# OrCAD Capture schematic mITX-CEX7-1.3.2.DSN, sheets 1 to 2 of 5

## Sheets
1 CEX7-Interface: size D; title: COM express type 7 interface; rev: 1.3
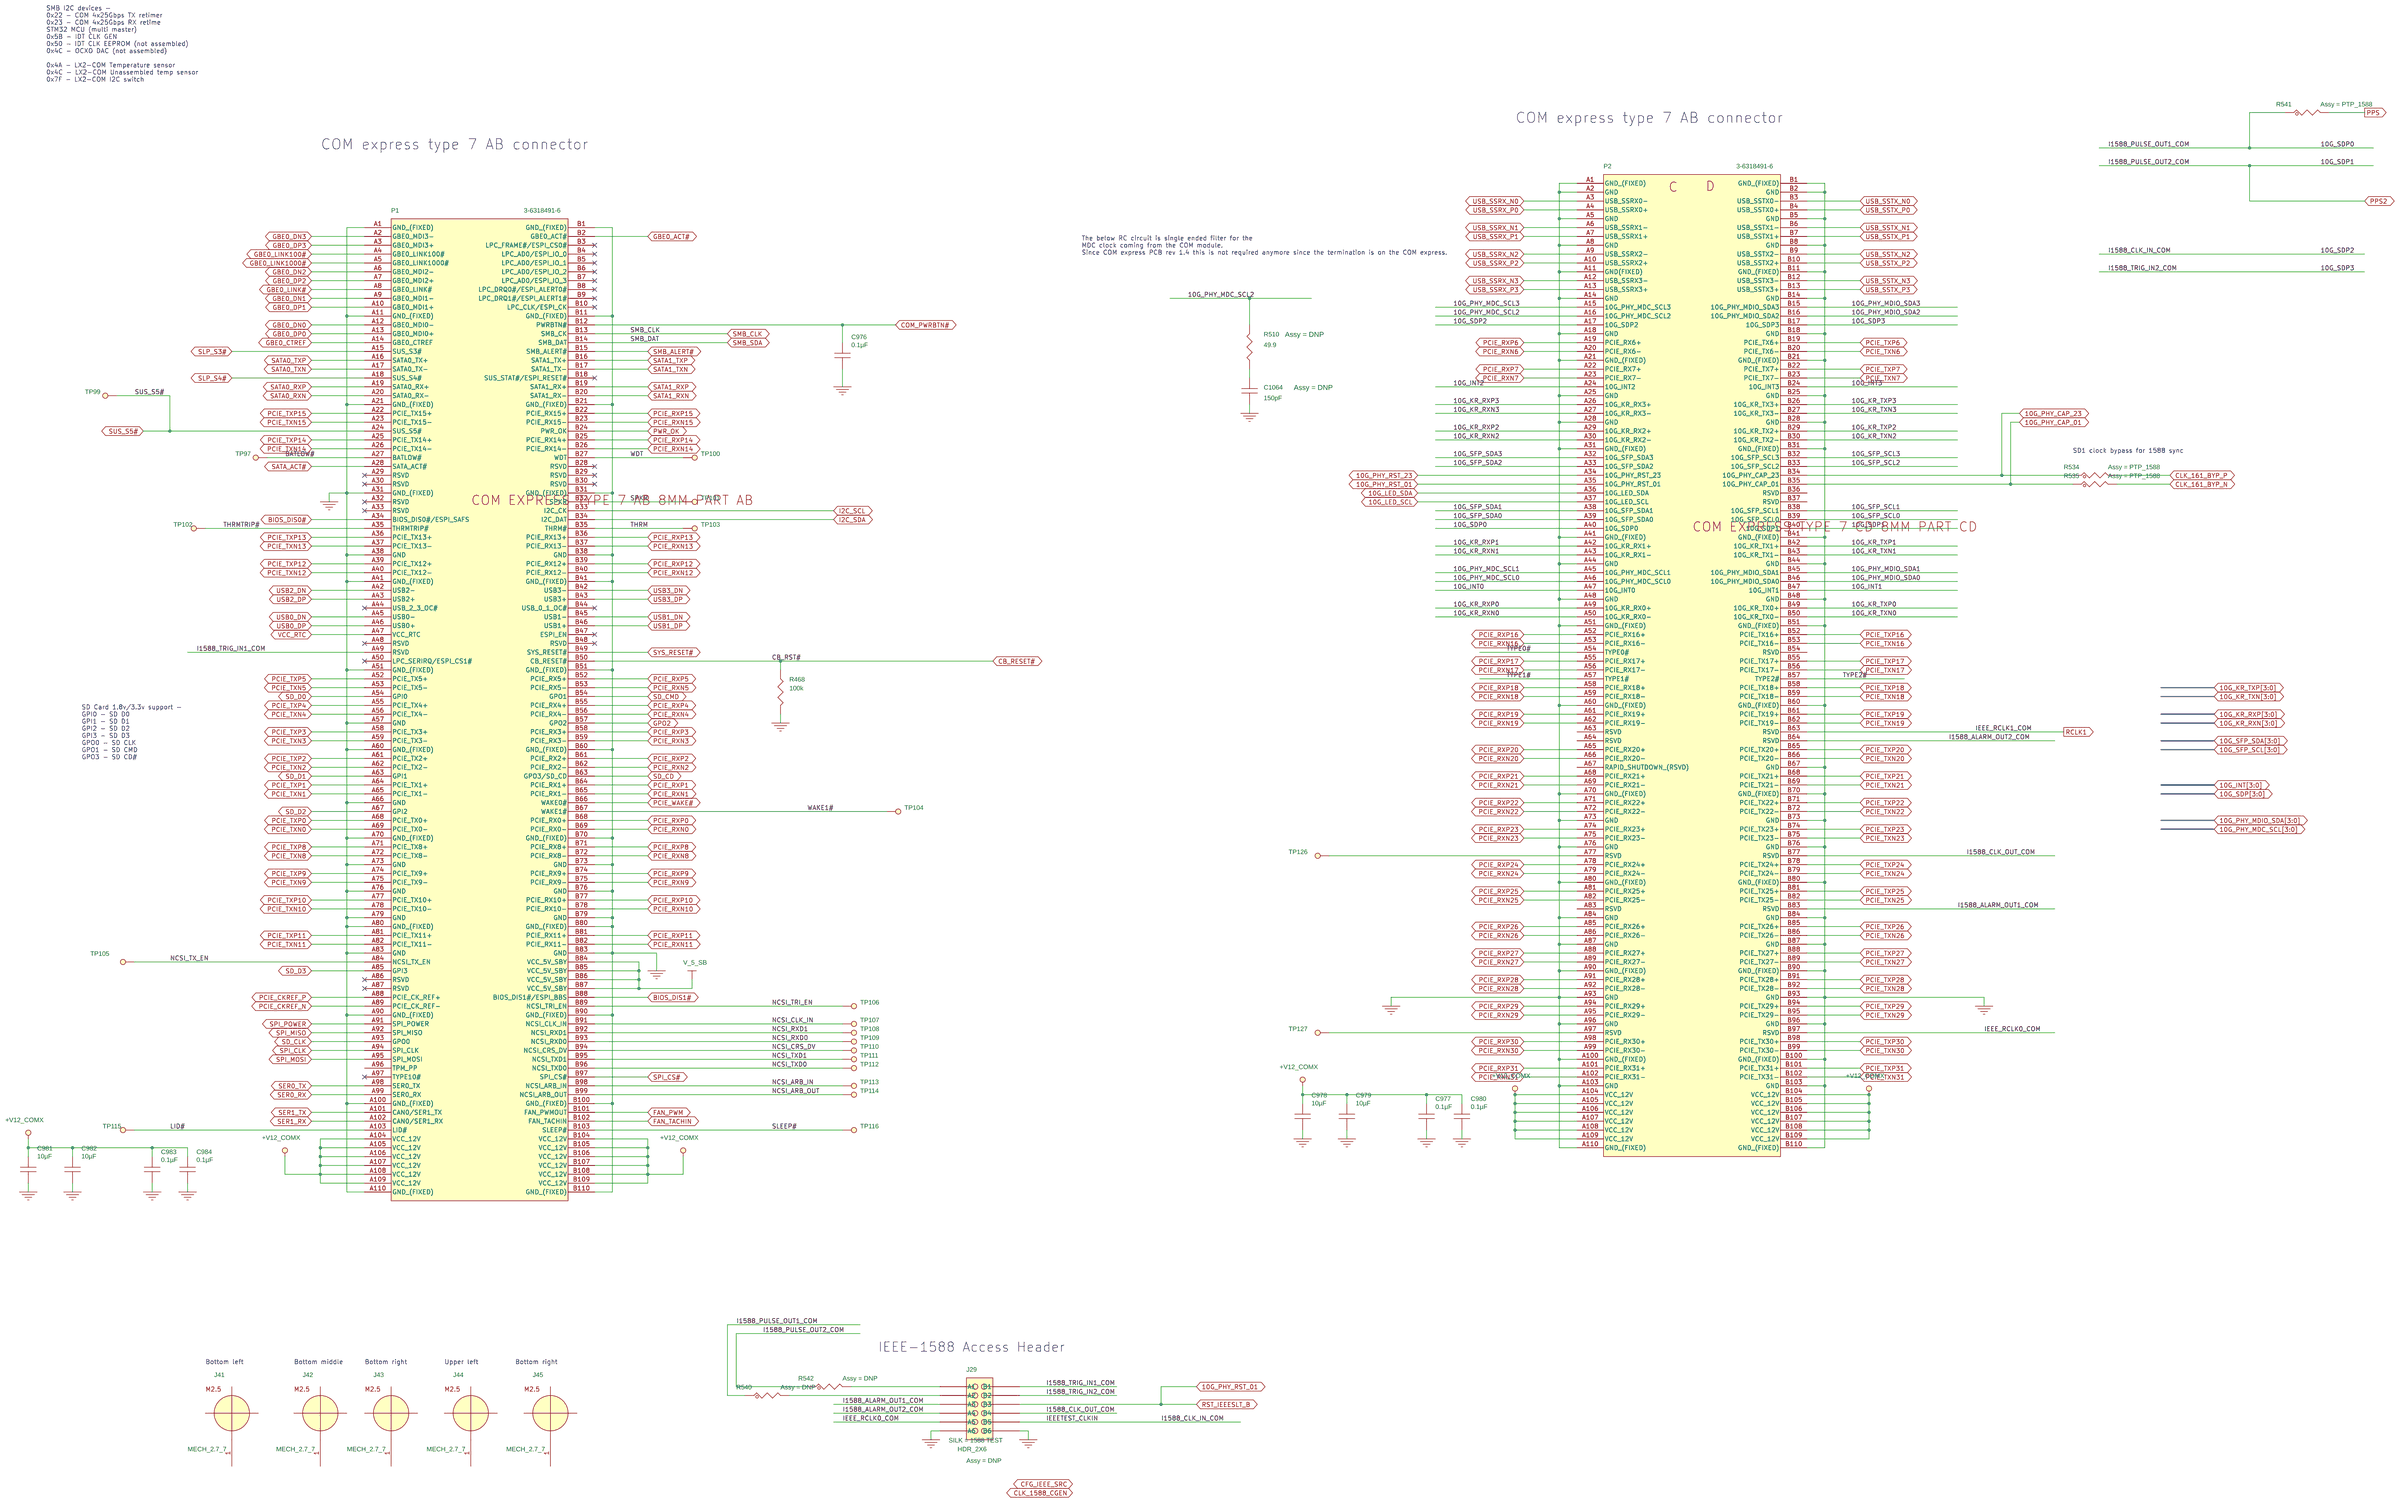
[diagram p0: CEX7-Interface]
2 Connectors: size D; title: PCIe, SATA, NVME, FANs, micro SD, RJ45 and QSFP28 connectors
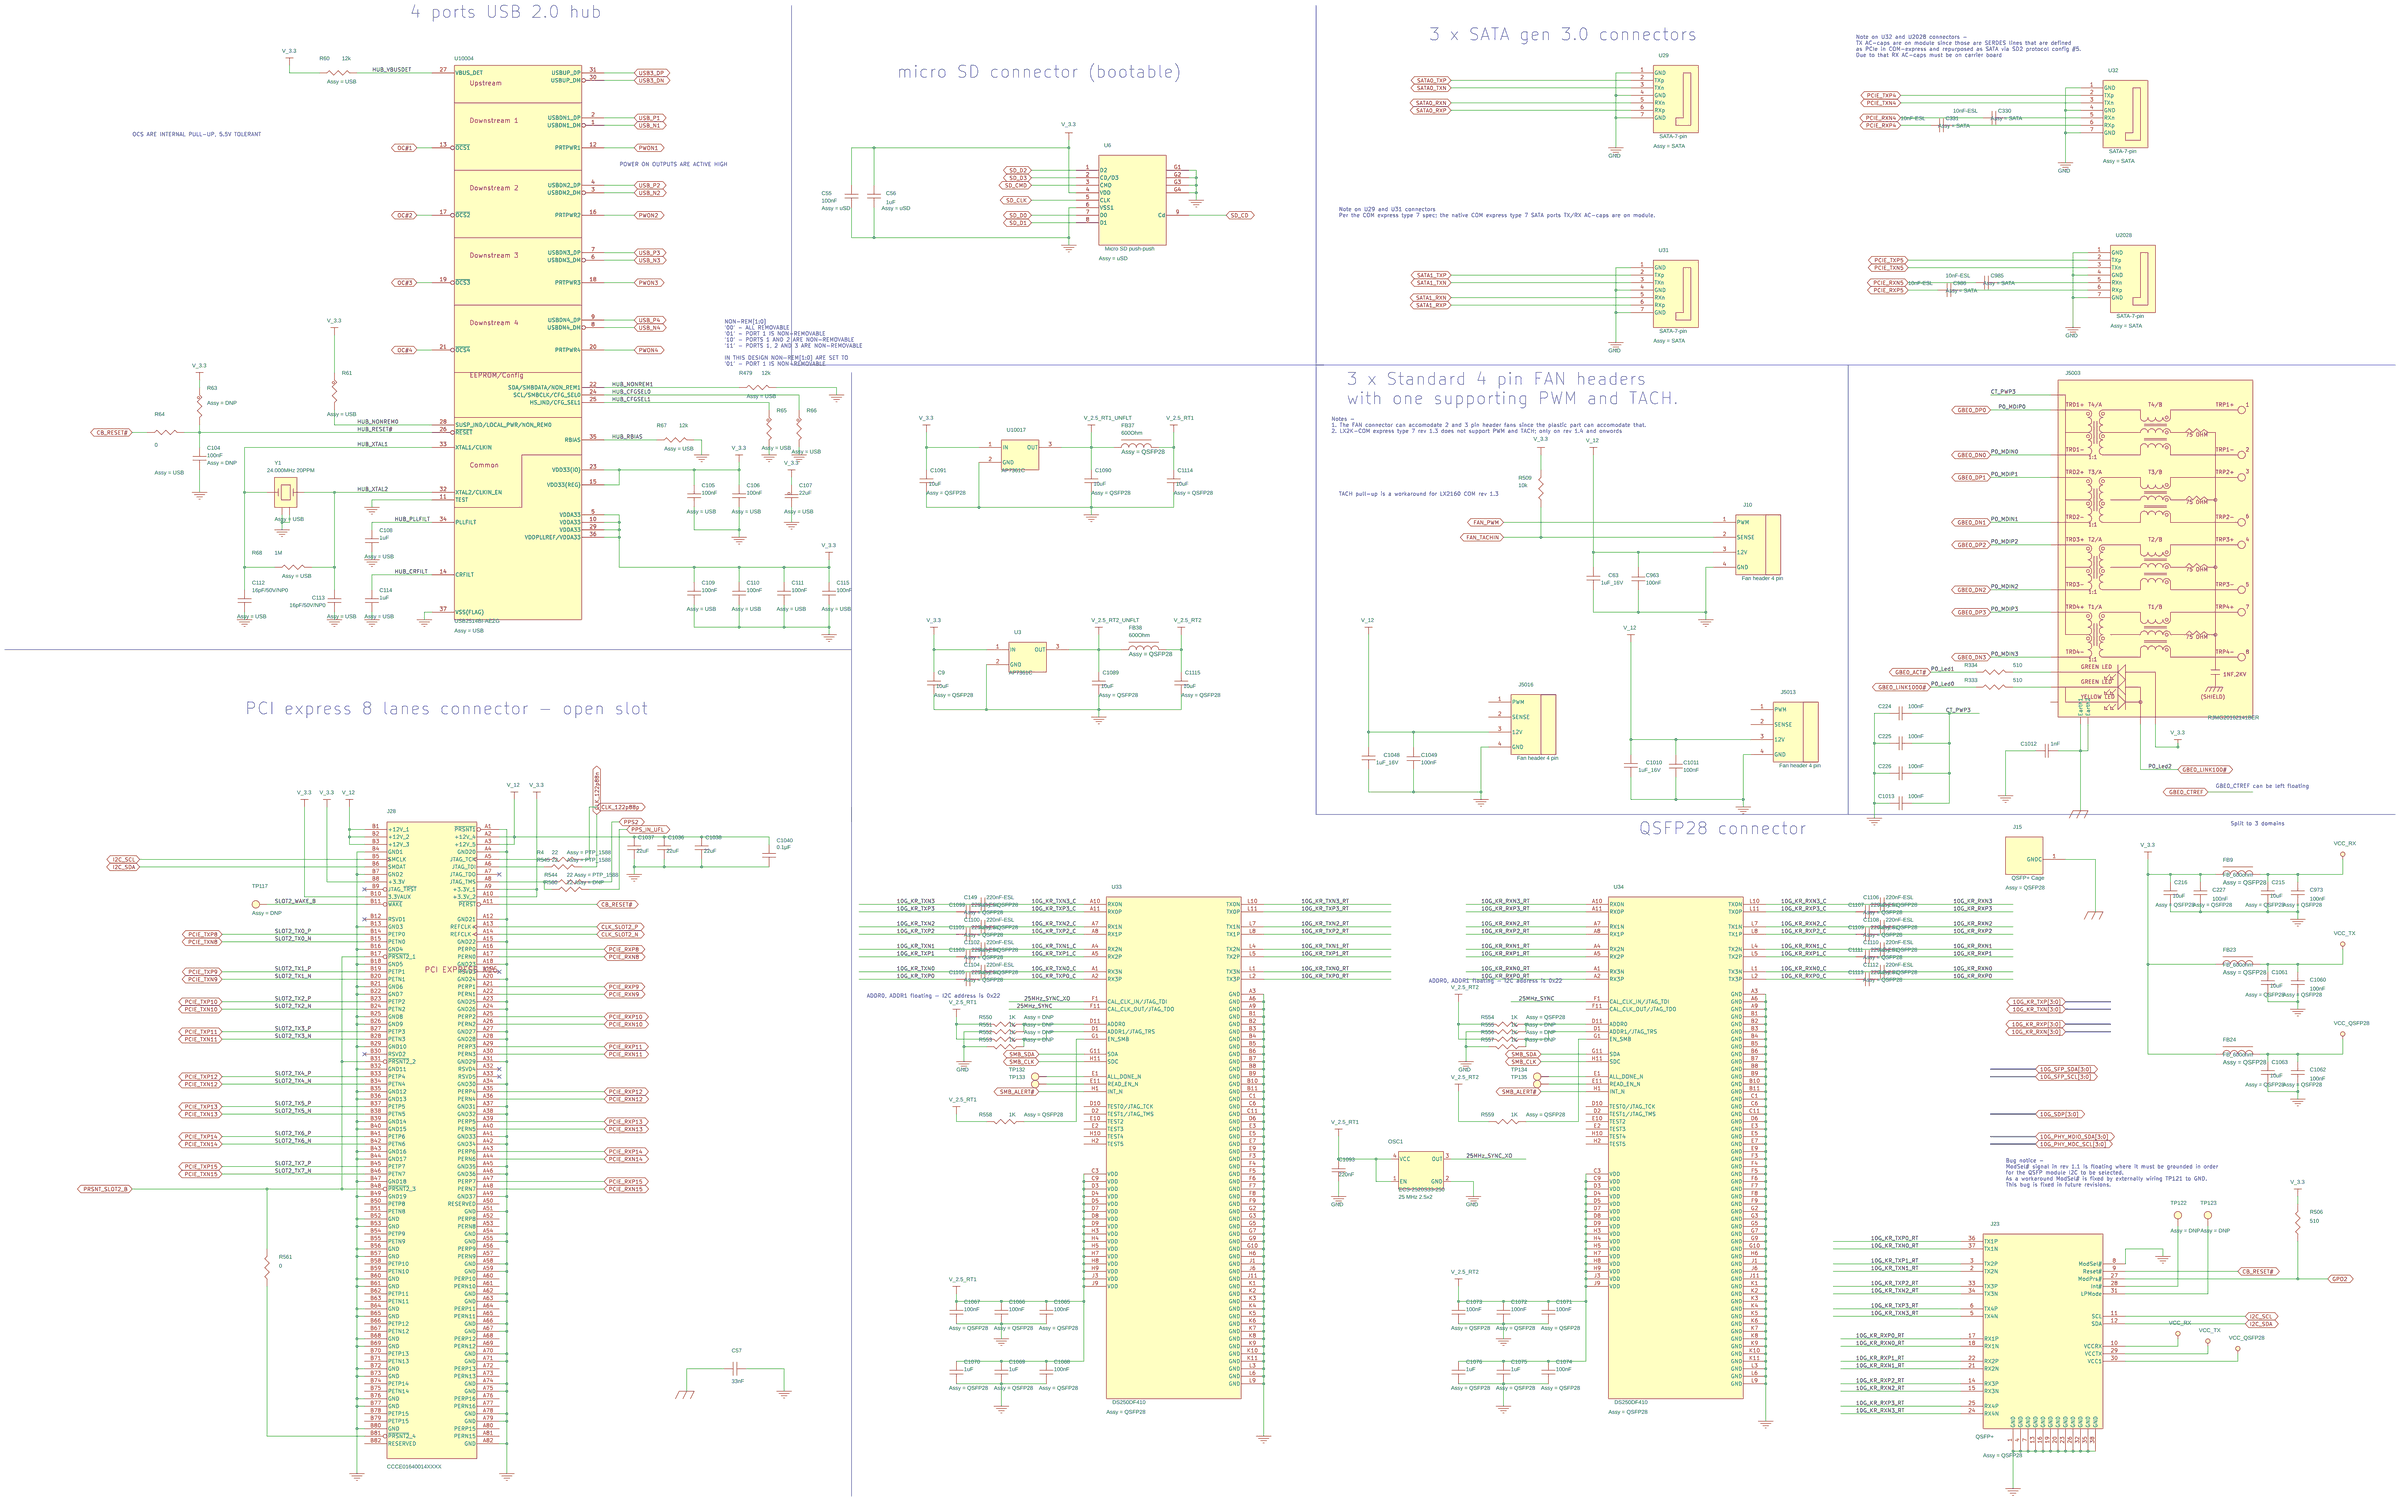
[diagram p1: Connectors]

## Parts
sheet CEX7-Interface
C976  0.1µF  [RC0402]
C977  0.1µF  [RC0402]
C978  10µF  [RC0805]
C979  10µF  [RC0805]
C980  0.1µF  [RC0402]
C981  10µF  [RC0805]
C982  10µF  [RC0805]
C983  0.1µF  [RC0402]
C984  0.1µF  [RC0402]
C1064  150pF
J29  HDR_2X6  [tsm2x6_smd]
J41  MECH_2.7_7  [MECH_2.5_4]
J42  MECH_2.7_7  [MECH_2.5_4]
J43  MECH_2.7_7  [MECH_2.5_4]
J44  MECH_2.7_7  [MECH_2.5_4]
J45  MECH_2.7_7  [MECH_2.5_4]
P1  3-6318491-6  [A107335-ND-AB]
P2  3-6318491-6  [A107335-ND-CD]
R468  100k  [RC0402]
R510  49.9
R534  0  [0402]
R535  0  [0402]
R540  0  [0402]
R541  0  [0402]
R542  0  [0402]
TP97  TESTPOINT  [TESTPOINT]
TP99  TESTPOINT  [TESTPOINT]
TP100  TESTPOINT  [TESTPOINT]
TP101  TESTPOINT  [TESTPOINT]
TP102  TESTPOINT  [TESTPOINT]
TP103  TESTPOINT  [TESTPOINT]
TP104  TESTPOINT  [TESTPOINT]
TP105  TESTPOINT  [TESTPOINT]
TP106  TESTPOINT  [TESTPOINT]
TP107  TESTPOINT  [TESTPOINT]
TP108  TESTPOINT  [TESTPOINT]
TP109  TESTPOINT  [TESTPOINT]
TP110  TESTPOINT  [TESTPOINT]
TP111  TESTPOINT  [TESTPOINT]
TP112  TESTPOINT  [TESTPOINT]
TP113  TESTPOINT  [TESTPOINT]
TP114  TESTPOINT  [TESTPOINT]
TP115  TESTPOINT  [TESTPOINT]
TP116  TESTPOINT  [TESTPOINT]
TP126  TESTPOINT  [TESTPOINT]
TP127  TESTPOINT  [TESTPOINT]
sheet Connectors
C9  10uF  [C0603]
C55  100nF
C56  1uF
C57  33nF
C63  1uF_16V
C104  100nF
C105  100nF
C106  100nF
C107  22uF
C108  1uF
C109  100nF
C110  100nF
C111  100nF
C112  16pF/50V/NP0  [1276-1646-1-ND]
C113  16pF/50V/NP0  [1276-1646-1-ND]
C114  1uF
C115  100nF
C149  220nF-ESL  [C0402]
C215  10uF
C216  10uF
C224  100nF
C225  100nF
C226  100nF
C227  100nF
C330  10nF-ESL
C331  10nF-ESL
C963  100nF
C973  100nF
C985  10nF-ESL
C986  10nF-ESL
C1010  1uF_16V
C1011  100nF
C1012  1nF
C1013  100nF
C1036  22uF
C1037  22uF
C1038  22uF
C1040  0.1µF  [RC0402]
C1048  1uF_16V
C1049  100nF
C1060  100nF
C1061  10uF
C1062  100nF
C1063  10uF
C1065  100nF
C1066  100nF
C1067  100nF
C1068  100nF
C1069  1uF
C1070  1uF
C1071  100nF
C1072  100nF
C1073  100nF
C1074  100nF
C1075  1uF
C1076  1uF
C1089  10uF  [C0603]
C1090  10uF  [C0603]
C1091  10uF  [C0603]
C1093  220nF  [C0402]
C1099  220nF-ESL  [C0402]
C1100  220nF-ESL  [C0402]
C1101  220nF-ESL  [C0402]
C1102  220nF-ESL  [C0402]
C1103  220nF-ESL  [C0402]
C1104  220nF-ESL  [C0402]
C1105  220nF-ESL  [C0402]
C1106  220nF-ESL  [C0402]
C1107  220nF-ESL  [C0402]
C1108  220nF-ESL  [C0402]
C1109  220nF-ESL  [C0402]
C1110  220nF-ESL  [C0402]
C1111  220nF-ESL  [C0402]
C1112  220nF-ESL  [C0402]
C1113  220nF-ESL  [C0402]
C1114  10uF  [C0603]
C1115  10uF  [C0603]
FB9  FB_600ohm
FB23  FB_600ohm
FB24  FB_600ohm
FB37  600Ohm  [L0603]
FB38  600Ohm  [L0603]
J10  Fan header 4 pin  [22-23-2041]
J15  QSFP+ Cage
J23  QSFP+
J28  CCCE01640014XXXX
J5003  RJMG20162141BER
J5013  Fan header 4 pin  [22-23-2041]
J5016  Fan header 4 pin  [22-23-2041]
OSC1  ECS-2520S33-250  [ECS-2520S33-250-FN-TR]
R4  22  [R0402]
R60  12k  [RC0402]
R61  100K
R63  100K
R64  0  [RC0402]
R65  100K
R66  100K
R67  12k  [RC0402]
R68  1M  [RC0402]
R333  510
R334  510
R479  12k  [RC0402]
R506  510
R509  10k
R544  22  [R0402]
R545  22  [R0402]
R550  1K
R551  1K
R552  1K
R553  1K
R554  1K
R555  1K
R556  1K
R557  1K
R558  1K
R559  1K
R560  22  [R0402]
R561  0  [RC0402]
TP117  TP
TP122  TP
TP123  TP
TP132  TP
TP133  TP
TP134  TP
TP135  TP
U3  AP7361C  [SOT223]
U6  Micro SD push-push  [CJ-WK21923-R6SS6]
U29  SATA-7-pin  [SATA-7-PIN]
U31  SATA-7-pin  [SATA-7-PIN]
U32  SATA-7-pin  [SATA-7-PIN]
U33  DS250DF410
U34  DS250DF410
U2028  SATA-7-pin  [SATA-7-PIN]
U10004  USB2514BI-AEZG  [USB2514BI-AEZG-ND]
U10017  AP7361C  [SOT223]
Y1  24.000MHz 20PPM  [SER3634CT-ND]

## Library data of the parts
C976 C977 C980 C983 C984 C1040 = CAP_CER_0.1UF_16V_10%_X7R_0402: SolidRun P/N: CA20013
C978 C979 C981 C982 = CAP_CER_10UF_25V_10%_X5R_0805: SolidRun P/N: CA40005
C1064 = Cap: CAP CER 0402 150pF 50V 5% COG; Assy: DNP; SolidRun P/N: CA20827
J29 = CONN_HDR_6X2: HDR 2X6 SMT 100MIL SP 380H AU; AGILE_PN: 211-75508; Assy: DNP; CAD_APPROVED: Yes; HEIGHT: 9.65mm; MFG_NAME01: SAMTEC; MFG_PN01: TSM-106-01-S-DV-A-P; ROHS: Yes; SILK: 1588 TEST; SolidRun P/N: CO00807
J41-J45 = MECH_0.5_4: SolidRun P/N: MCH00072
P1 = COM-EXPRESS_BASE_TYP_7_CONN_AB: SolidRun P/N: CO00676
P2 = COM-EXPRESS_BASE_TYP_7_CONN_CD: SolidRun P/N: CO00676
R468 = RES_100K_OHM_1_16W_1%_0402_SMD: SolidRun P/N: RE20482
R510 = Resistor: RES 0402 1/16W 49.9 1%; Assy: DNP; SolidRun P/N: RE20011
R534 R535 R541 = RES: RES MF ZERO OHM 1/10W -- 0402; AGILE_PN: 470-79965; Assy: PTP_1588; CAD_APPROVED: Yes; FPLIST: RC0402_25,RC0402_HD,RC0402_X2,0402_CC; PRIORITY_PN: RE20009; ROHS: Yes; SIGNAL_MODEL: DEFAULT_RESISTOR_0.001OHM_2_1; SolidRun P/N: RE20009
R540 R542 = RES: RES MF ZERO OHM 1/10W -- 0402; AGILE_PN: 470-79965; Assy: DNP; CAD_APPROVED: Yes; FPLIST: RC0402_25,RC0402_HD,RC0402_X2,0402_CC; PRIORITY_PN: RE20009; ROHS: Yes; SIGNAL_MODEL: DEFAULT_RESISTOR_0.001OHM_2_1; SolidRun P/N: RE20009
TP97 TP99-TP116 TP126 TP127 = TESTPOINT: Assy: DNP; SolidRun P/N: TP00001
C9 C1089-C1091 C1114 C1115 = Cap: CAP CER 0603 10UF 6.3V 10% X5R; Assy: QSFP28; Manufacturer: Samsung; Manufacturer Name: Samsung; Manufacturer P/N: CL10A106KQ8NNNC; Part Number: C1060805-X5R-16V; SolidRun P/N: CA30001; Updated: 2016-02-10 17:13:33; Datasheet: <null>
C55 = Cap: Assy: uSD; SolidRun P/N: CA20001
C56 = Cap: Assy: uSD; SolidRun P/N: CA20005
C57 = Cap: SolidRun P/N: CA20011
C63 C1010 C1048 = Cap: SolidRun P/N: CA30013
C104 = Cap: CAP CER 0402 100nF 10V 10% X7R; Assy: DNP; SolidRun P/N: CA20001
C105 C106 C109-C111 C115 = Cap: CAP CER 0402 100nF 10V 10% X7R; Assy: USB; SolidRun P/N: CA20001
C107 = CAP_NP: CAP CER 22UF 6.3V 20% X5R 0603; Assy: USB; SolidRun P/N: CA30002
C108 C114 = Cap: CAP CER 1uF 10V 10% X5R 0402; Assy: USB; SolidRun P/N: CA20005
C112 C113 = CAP_CER_16PF_50V_5%_NP0_0402: Assy: USB; SolidRun P/N: CA20134
C149 C1099-C1113 = Cap: CAP CER 220nF 16V 10% X7R 0402; Assy: QSFP28; FPLIST: 0402_SQR21,0402_RND,0402; Manufacturer: CAPAX; Manufacturer P/N: 0402X224K250SNT; Part Number: 0402X224K250SNT; SolidRun P/N: CA20826; Updated: 2015-02-17 20:35:06; Datasheet: <null>
C215 C216 C1061 C1063 = Cap: CAP CER 10UF 6.3V 10% X5R 0603; Assy: QSFP28; SolidRun P/N: CA30001
C224-C226 C1013 = CAP_NP1: CAP CER 0.1uF ±10% 50V X7R 0402; SolidRun P/N: CA20147
C227 C973 C1060 C1062 = Cap: CHIP CAP 0.1uF 6.3V 0402 X5R; Assy: QSFP28; SolidRun P/N: CA20001
C330 C331 C985 C986 = Cap: Assy: SATA; SolidRun P/N: CA20002
C963 C1011 C1049 = Cap: SolidRun P/N: CA20001
C1012 = CAP_NP1: CAP CER 1nF ±10% 1KV X7R 1206; SolidRun P/N: CA50002
C1036-C1038 = Cap: SolidRun P/N: CA60006
C1065-C1068 C1071-C1074 = Cap: CAP CER 0402 100nF 10V 10% X7R; Assy: QSFP28; SolidRun P/N: CA20001
C1069 C1070 C1075 C1076 = Cap: CAP CER 1uF 10V 10% X5R 0402; Assy: QSFP28; SolidRun P/N: CA20005
C1093 = CAP_NP1: CAP CER 0.22UF 16V X7R 0402; Assy: QSFP28; Digikey P/N: 490-5418-2-ND; Manufacturer: Murata Electronics North America; Part Num#: GRM155R71C224KA12D; Rating: 16V; SolidRun P/N: CA20820; Vol: 10%
FB9 FB23 FB24 = Ferrite_Bead_v3: Multilayer Ferrite Chip Beads 0603 600ohm 1.3A +/-25%; Assy: QSFP28; SolidRun P/N: IN00068
FB37 FB38 = Ferrite_Bead_v3: Multilayer Ferrite Chip Beads 600 OHM; Assy: QSFP28; Manufacturer: chilisin; Manufacturer P/N: PBY160808T-601Y-N; Part Number: PBY160808T-601Y-N; SolidRun P/N: IN00012; Updated: 2015-02-17 20:35:06; Datasheet: http://www.chilisin.com.tw/proimages/product_line_up_pdf/Chip%20Beads%20PB%20Series.pdf
J10 J5013 J5016 = Fan_header_4_pin: SolidRun P/N: CO00640
J15 = QSFP+_Cage: Assy: QSFP28; SolidRun P/N: CO00707
J23 = QSFP+: Assy: QSFP28; SolidRun P/N: CO00706
J28 = CONN_PCI_EXPRESS_X8_0: CON 2X62 PCI EXPRESS SMT 1MM SP 320H AU; SolidRun P/N: CO00808
J5003 = J-RJMG20162141BER-FCI: CONN MAGJACK 1PORT 1000 BASE-T; SolidRun P/N: CO00673
OSC1 = OSC_ECS-2520S: 25MHz XO (Standard) HCMOS Oscillator 3.3V Enable/Disable 4-SMD, No Lead; Assy: QSFP28; Digikey P/N: ECS Inc.; Manufacturer: ECS Inc.; Rating: 25 MHz 2.5x2; SolidRun P/N: OC00039; Datasheet: https://www.ecsxtal.com/store/pdf/ECS-2520S.pdf
R4 R544 R545 = Resistor: RES 0402 1/16W 22? 5%; Assy: PTP_1588; Manufacturer: Yageo; Manufacturer P/N: RC0402JR-0722RL; Part Number: R2200402-1%; Power: <null>; SolidRun P/N: RE20021; Tolerance: 5%; Datasheet: <null>
R60 R67 R479 = RES_12.0K_OHM_1_16W_1%_0402_SMD: Assy: USB; SolidRun P/N: RE20462
R61 R65 R66 = RES: RES MF 100K 1/16W 0402; Assy: USB; SolidRun P/N: RE20015
R63 = RES: RES MF 100K 1/16W 0402; Assy: DNP; SolidRun P/N: RE20015
R64 = RES_0.0_OHM_1_16W_0402_SMD: Assy: USB; SolidRun P/N: RE20009
R68 = RES_1.00M_OHM_1_16W_1%_0402_SMD: Assy: USB; SolidRun P/N: RE20416
R333 R334 R506 = RES1: RES SMD 510 OHM 5% 1/16W 0402; SolidRun P/N: RE20022
R509 = Resistor: RES 0402 1/16W 10K? 1%; SolidRun P/N: RE20013
R550-R553 R555-R557 = Resistor: RES 0402 1/16W 1K 5%; Assy: DNP; SolidRun P/N: RE20010
R554 R558 R559 = Resistor: RES 0402 1/16W 1K 5%; Assy: QSFP28; SolidRun P/N: RE20010
R560 = Resistor: RES 0402 1/16W 22? 5%; Assy: DNP; Manufacturer: Yageo; Manufacturer P/N: RC0402JR-0722RL; Part Number: R2200402-1%; Power: <null>; SolidRun P/N: RE20021; Tolerance: 5%; Datasheet: <null>
R561 = RES_0.0_OHM_1_16W_0402_SMD: SolidRun P/N: RE20009
TP117 TP122 TP123 TP132-TP135 = TestPoint: Assy: DNP; SolidRun P/N: TP00001
U3 U10017 = AP7361C_0: 1A, 2.5V fixed output voltage LDO; Assy: QSFP28; Manufacturer: Diodes; Manufacturer Name: Diodes; Manufacturer P/N: AP7361C-25E-13; SolidRun P/N: IC01072; Datasheet: http://www.diodes.com/_files/datasheets/AP7361.pdf
U6 = CJ-WK21923-R6SS6_0: Assy: uSD; SolidRun P/N: CO00091
U29 U31 U32 U2028 = SATA-7-pin: Assy: SATA; SolidRun P/N: CO00581
U33 U34 = DS250DF410: Assy: QSFP28; SolidRun P/N: IC01524
U10004 = IC_USB_2.0_HUB_4P_IND_36QFNE3: Assy: USB; SolidRun P/N: IC01084
Y1 = CRYSTAL_24MHZ_9PF_40Ohm_20ppm: Assy: USB; SolidRun P/N: OC00003

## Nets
3.3V: C9.1 C55.1 C56.1 C105.1 C106.1 C107.1 C109.1 C110.1 C111.1 C115.1 C216.1 C227.1 C1091.1 FB9.1 FB23.1 FB24.1 J28.A9(+3.3V_1) J28.A10(+3.3V_2) J28.B8(+3.3V) J28.B10(3.3VAUX) J5003.13 R60.1 R61.1 R63.1 R506.2 R509.2 U3.1(IN) U6.4(VDD) U10004.5(VDDA33) U10004.10(VDDA33) U10004.15(VDD33(REG)) U10004.23(VDD33(IO)) U10004.29(VDDA33) U10004.36(VDDPLLREF/VDDA33) U10017.1(IN) ; also on sheet 3 4 5
+V12_COMX: C63.1 C963.2 C977.1 C978.1 C979.1 C980.1 C981.1 C982.1 C983.1 C984.1 C1010.1 C1011.2 C1036.1 C1037.1 C1038.1 C1040.1 C1048.1 C1049.2 J10.3(12V) J28.A2(+12V_4) J28.A3(+12V_5) J28.B1(+12V_1) J28.B2(+12V_2) J28.B3(+12V_3) J5013.3(12V) J5016.3(12V) P1.A104(VCC_12V) P1.A105(VCC_12V) P1.A106(VCC_12V) P1.A107(VCC_12V) P1.A108(VCC_12V) P1.A109(VCC_12V) P1.B104(VCC_12V) P1.B105(VCC_12V) P1.B106(VCC_12V) P1.B107(VCC_12V) P1.B108(VCC_12V) P1.B109(VCC_12V) P2.A104(VCC_12V) P2.A105(VCC_12V) P2.A106(VCC_12V) P2.A107(VCC_12V) P2.A108(VCC_12V) P2.A109(VCC_12V) P2.B104(VCC_12V) P2.B105(VCC_12V) P2.B106(VCC_12V) P2.B107(VCC_12V) P2.B108(VCC_12V) P2.B109(VCC_12V) ; also on sheet 3 4
GND: C9.2 C55.2 C56.2 C57.2 C63.2 C104.2 C105.2 C106.2 C107.2 C108.2 C109.2 C110.2 C111.2 C112.2 C113.2 C114.2 C115.2 C215.2 C216.2 C224.1 C225.1 C226.1 C227.2 C963.1 C973.2 C976.2 C977.2 C978.2 C979.2 C980.2 C981.2 C982.2 C983.2 C984.2 C1010.2 C1011.1 C1012.2 C1013.1 C1036.2 C1037.2 C1038.2 C1040.2 C1048.2 C1049.1 C1060.2 C1061.2 C1062.2 C1063.2 C1064.2 C1065.2 C1066.2 C1067.2 C1068.2 C1069.2 C1070.2 C1071.2 C1072.2 C1073.2 C1074.2 C1075.2 C1076.2 C1089.2 C1090.2 C1091.2 C1093.2 C1114.2 C1115.2 J10.4(GND) J23.1(GND) J23.4(GND) J23.7(GND) J23.8(ModSeI#) J23.13(GND) J23.16(GND) J23.19(GND) J23.20(GND) J23.23(GND) J23.26(GND) J23.32(GND) J23.35(GND) J23.38(GND) J28.A1(~{PRSNT1}) J28.A4(GND20) J28.A12(GND21) J28.A15(GND22) J28.A18(GND23) J28.A20(GND24) J28.A23(GND25) J28.A24(GND26) J28.A27(GND27) J28.A28(GND28) J28.A31(GND29) J28.A34(GND30) J28.A37(GND31) J28.A38(GND32) J28.A41(GND33) J28.A42(GND34) J28.A45(GND35) J28.A46(GND36) J28.A49(GND37) J28.A51(GND) J28.A54(GND) J28.A55(GND) J28.A58(GND) J28.A59(GND) J28.A62(GND) J28.A63(GND) J28.A66(GND) J28.A67(GND) J28.A70(GND) J28.A71(GND) J28.A74(GND) J28.A75(GND) J28.A78(GND) J28.A79(GND) J28.A82(GND) J28.B4(GND1) J28.B7(GND2) J28.B13(GND3) J28.B16(GND4) J28.B18(GND5) J28.B21(GND6) J28.B22(GND7) J28.B25(GND8) J28.B26(GND9) J28.B29(GND10) J28.B32(GND11) J28.B35(GND12) J28.B36(GND13) J28.B39(GND14) J28.B40(GND15) J28.B43(GND16) J28.B44(GND17) J28.B47(GND18) J28.B49(GND19) J28.B52(GND) J28.B53(GND) J28.B56(GND) J28.B57(GND) J28.B60(GND) J28.B61(GND) J28.B64(GND) J28.B65(GND) J28.B68(GND) J28.B69(GND) J28.B72(GND) J28.B73(GND) J28.B76(GND) J28.B77(GND) J28.B80(GND) J29.11(A6) J29.12(B6) J5013.4(GND) J5016.4(GND) OSC1.2(GND) P1.A1(GND_(FIXED)) P1.A11(GND_(FIXED)) P1.A21(GND_(FIXED)) P1.A31(GND_(FIXED)) P1.A38(GND) P1.A41(GND_(FIXED)) P1.A51(GND_(FIXED)) P1.A57(GND) P1.A60(GND_(FIXED)) P1.A66(GND) P1.A70(GND_(FIXED)) P1.A73(GND) P1.A76(GND) P1.A79(GND) P1.A80(GND_(FIXED)) P1.A83(GND) P1.A90(GND_(FIXED)) P1.A100(GND_(FIXED)) P1.A110(GND_(FIXED)) P1.B1(GND_(FIXED)) P1.B11(GND_(FIXED)) P1.B21(GND_(FIXED)) P1.B31(GND_(FIXED)) P1.B38(GND) P1.B41(GND_(FIXED)) P1.B51(GND_(FIXED)) P1.B60(GND_(FIXED)) P1.B70(GND_(FIXED)) P1.B73(GND) P1.B76(GND) P1.B79(GND) P1.B80(GND_(FIXED)) P1.B83(GND) P1.B90(GND_(FIXED)) P1.B100(GND_(FIXED)) P1.B110(GND_(FIXED)) P2.A1(GND_(FIXED)) P2.A2(GND) P2.A5(GND) P2.A8(GND) P2.A11(GND(FIXED)) P2.A14(GND) P2.A18(GND) P2.A21(GND_(FIXED)) P2.A25(GND) P2.A28(GND) P2.A31(GND_(FIXED)) P2.A41(GND_(FIXED)) P2.A44(GND) P2.A48(GND) P2.A51(GND_(FIXED)) P2.A60(GND_(FIXED)) P2.A70(GND_(FIXED)) P2.A73(GND) P2.A76(GND) P2.A80(GND_(FIXED)) P2.A84(GND) P2.A87(GND) P2.A90(GND_(FIXED)) P2.A93(GND) P2.A96(GND) P2.A100(GND_(FIXED)) P2.A103(GND) P2.A110(GND_(FIXED)) P2.B1(GND_(FIXED)) P2.B2(GND) P2.B5(GND) P2.B8(GND) P2.B11(GND_(FIXED)) P2.B14(GND) P2.B18(GND) P2.B21(GND_(FIXED)) P2.B25(GND) P2.B28(GND) P2.B31(GND_(FIXED)) P2.B41(GND_(FIXED)) P2.B44(GND) P2.B48(GND) P2.B51(GND_(FIXED)) P2.B60(GND_(FIXED)) P2.B67(GND) P2.B70(GND_(FIXED)) P2.B73(GND) P2.B76(GND) P2.B80(GND_(FIXED)) P2.B84(GND) P2.B87(GND) P2.B90(GND_(FIXED)) P2.B93(GND) P2.B96(GND) P2.B100(GND_(FIXED)) P2.B103(GND) P2.B110(GND_(FIXED)) R65.2 R66.2 R67.2 R468.2 R479.2 R551.2 R553.2 R555.2 R557.2 U3.2(GND) U6.6(VSS1) U6.G1 U6.G2 U6.G3 U6.G4 U29.1(GND) U29.4(GND) U29.7(GND) U31.1(GND) U31.4(GND) U31.7(GND) U32.1(GND) U32.4(GND) U32.7(GND) U33.A3(GND) U33.A6(GND) U33.A9(GND) U33.B1(GND) U33.B2(GND) U33.B3(GND) U33.B4(GND) U33.B5(GND) U33.B6(GND) U33.B7(GND) U33.B8(GND) U33.B9(GND) U33.B10(GND) U33.B11(GND) U33.C1(GND) U33.C6(GND) U33.C11(GND) U33.D6(GND) U33.E3(GND) U33.E5(GND) U33.E7(GND) U33.E9(GND) U33.F3(GND) U33.F4(GND) U33.F5(GND) U33.F6(GND) U33.F7(GND) U33.F8(GND) U33.F9(GND) U33.G2(GND) U33.G3(GND) U33.G5(GND) U33.G7(GND) U33.G9(GND) U33.G10(GND) U33.H6(GND) U33.J1(GND) U33.J6(GND) U33.J11(GND) U33.K1(GND) U33.K2(GND) U33.K3(GND) U33.K4(GND) U33.K5(GND) U33.K6(GND) U33.K7(GND) U33.K8(GND) U33.K9(GND) U33.K10(GND) U33.K11(GND) U33.L3(GND) U33.L6(GND) U33.L9(GND) U34.A3(GND) U34.A6(GND) U34.A9(GND) U34.B1(GND) U34.B2(GND) U34.B3(GND) U34.B4(GND) U34.B5(GND) U34.B6(GND) U34.B7(GND) U34.B8(GND) U34.B9(GND) U34.B10(GND) U34.B11(GND) U34.C1(GND) U34.C6(GND) U34.C11(GND) U34.D6(GND) U34.E3(GND) U34.E5(GND) U34.E7(GND) U34.E9(GND) U34.F3(GND) U34.F4(GND) U34.F5(GND) U34.F6(GND) U34.F7(GND) U34.F8(GND) U34.F9(GND) U34.G2(GND) U34.G3(GND) U34.G5(GND) U34.G7(GND) U34.G9(GND) U34.G10(GND) U34.H6(GND) U34.J1(GND) U34.J6(GND) U34.J11(GND) U34.K1(GND) U34.K2(GND) U34.K3(GND) U34.K4(GND) U34.K5(GND) U34.K6(GND) U34.K7(GND) U34.K8(GND) U34.K9(GND) U34.K10(GND) U34.K11(GND) U34.L3(GND) U34.L6(GND) U34.L9(GND) U2028.1(GND) U2028.4(GND) U2028.7(GND) U10004.11(TEST) U10004.37(VSS(FLAG)) U10017.2(GND) Y1.2 Y1.4 ; also on sheet 3 4 5
GNDC: C57.1 C1012.1 J15.1(GNDC) J5003.SH1(Earth1) J5003.SH2(Earth2) ; also on sheet 3 4
VCC_QSFP28: C1062.1 C1063.1 FB24.2 J23.30(VCC1)
VCC_RTC: P1.A47(VCC_RTC) ; also on sheet 3
VCC_RX: C215.1 C973.1 FB9.2 J23.10(VCCRX)
VCC_TX: C1060.1 C1061.1 FB23.2 J23.29(VCCTX)
10G_INT0: P2.A47(10G_INT0) ; also on sheet 4
10G_INT1: P2.B47(10G_INT1) ; also on sheet 4
10G_INT2: P2.A24(10G_INT2) ; also on sheet 4
10G_INT3: P2.B24(10G_INT3) ; also on sheet 4
10G_KR_RXN0: C1112.1 P2.A50(10G_KR_RX0-)
10G_KR_RXN0_C: C1112.2 U34.L1(TX3N)
10G_KR_RXN0_RT: J23.18(RX1N) U34.A1(RX3N)
10G_KR_RXN1: C1110.1 P2.A43(10G_KR_RX1-)
10G_KR_RXN1_C: C1110.2 U34.L4(TX2N)
10G_KR_RXN1_RT: J23.21(RX2N) U34.A4(RX2N)
10G_KR_RXN2: C1108.1 P2.A30(10G_KR_RX2-)
10G_KR_RXN2_C: C1108.2 U34.L7(TX1N)
10G_KR_RXN2_RT: J23.15(RX3N) U34.A7(RX1N)
10G_KR_RXN3: C1106.1 P2.A27(10G_KR_RX3-)
10G_KR_RXN3_C: C1106.2 U34.L10(TX0N)
10G_KR_RXN3_RT: J23.24(RX4N) U34.A10(RX0N)
10G_KR_RXP0: C1113.1 P2.A49(10G_KR_RX0+)
10G_KR_RXP0_C: C1113.2 U34.L2(TX3P)
10G_KR_RXP0_RT: J23.17(RX1P) U34.A2(RX3P)
10G_KR_RXP1: C1111.1 P2.A42(10G_KR_RX1+)
10G_KR_RXP1_C: C1111.2 U34.L5(TX2P)
10G_KR_RXP1_RT: J23.22(RX2P) U34.A5(RX2P)
10G_KR_RXP2: C1109.1 P2.A29(10G_KR_RX2+)
10G_KR_RXP2_C: C1109.2 U34.L8(TX1P)
10G_KR_RXP2_RT: J23.14(RX3P) U34.A8(RX1P)
10G_KR_RXP3: C1107.1 P2.A26(10G_KR_RX3+)
10G_KR_RXP3_C: C1107.2 U34.L11(TX0P)
10G_KR_RXP3_RT: J23.25(RX4P) U34.A11(RX0P)
10G_KR_TXN0: C1104.2 P2.B50(10G_KR_TX0-)
10G_KR_TXN0_C: C1104.1 U33.A1(RX3N)
10G_KR_TXN0_RT: J23.37(TX1N) U33.L1(TX3N)
10G_KR_TXN1: C1102.2 P2.B43(10G_KR_TX1-)
10G_KR_TXN1_C: C1102.1 U33.A4(RX2N)
10G_KR_TXN1_RT: J23.2(TX2N) U33.L4(TX2N)
10G_KR_TXN2: C1100.2 P2.B30(10G_KR_TX2-)
10G_KR_TXN2_C: C1100.1 U33.A7(RX1N)
10G_KR_TXN2_RT: J23.34(TX3N) U33.L7(TX1N)
10G_KR_TXN3: C149.2 P2.B27(10G_KR_TX3-)
10G_KR_TXN3_C: C149.1 U33.A10(RX0N)
10G_KR_TXN3_RT: J23.5(TX4N) U33.L10(TX0N)
10G_KR_TXP0: C1105.2 P2.B49(10G_KR_TX0+)
10G_KR_TXP0_C: C1105.1 U33.A2(RX3P)
10G_KR_TXP0_RT: J23.36(TX1P) U33.L2(TX3P)
10G_KR_TXP1: C1103.2 P2.B42(10G_KR_TX1+)
10G_KR_TXP1_C: C1103.1 U33.A5(RX2P)
10G_KR_TXP1_RT: J23.3(TX2P) U33.L5(TX2P)
10G_KR_TXP2: C1101.2 P2.B29(10G_KR_TX2+)
10G_KR_TXP2_C: C1101.1 U33.A8(RX1P)
10G_KR_TXP2_RT: J23.33(TX3P) U33.L8(TX1P)
10G_KR_TXP3: C1099.2 P2.B26(10G_KR_TX3+)
10G_KR_TXP3_C: C1099.1 U33.A11(RX0P)
10G_KR_TXP3_RT: J23.6(TX4P) U33.L11(TX0P)
10G_LED_SCL: P2.A37(10G_LED_SCL)
10G_LED_SDA: P2.A36(10G_LED_SDA)
10G_PHY_CAP_01: P2.B35(10G_PHY_CAP_01) R535.1
10G_PHY_CAP_23: P2.B34(10G_PHY_CAP_23) R534.1
10G_PHY_MDC_SCL0: P2.A46(10G_PHY_MDC_SCL0)
10G_PHY_MDC_SCL1: P2.A45(10G_PHY_MDC_SCL1)
10G_PHY_MDC_SCL2: P2.A16(10G_PHY_MDC_SCL2) R510.1
10G_PHY_MDC_SCL3: P2.A15(10G_PHY_MDC_SCL3)
10G_PHY_MDIO_SDA0: P2.B46(10G_PHY_MDIO_SDA0)
10G_PHY_MDIO_SDA1: P2.B45(10G_PHY_MDIO_SDA1)
10G_PHY_MDIO_SDA2: P2.B16(10G_PHY_MDIO_SDA2)
10G_PHY_MDIO_SDA3: P2.B15(10G_PHY_MDIO_SDA3)
10G_PHY_RST_01: J29.6(B3) P2.A35(10G_PHY_RST_01)
10G_PHY_RST_23: P2.A34(10G_PHY_RST_23)
10G_SDP0: P2.A40(10G_SDP0) R540.1 R541.1
10G_SDP1: P2.B40(10G_SDP1) R542.1 R544.2
10G_SDP2: J29.10(B5) P2.A17(10G_SDP2)
10G_SDP3: J29.4(B2) P2.B17(10G_SDP3)
10G_SFP_SCL0: P2.B39(10G_SFP_SCL0) ; also on sheet 4
10G_SFP_SCL1: P2.B38(10G_SFP_SCL1) ; also on sheet 4
10G_SFP_SCL2: P2.B33(10G_SFP_SCL2) ; also on sheet 4
10G_SFP_SCL3: P2.B32(10G_SFP_SCL3) ; also on sheet 4
10G_SFP_SDA0: P2.A39(10G_SFP_SDA0) ; also on sheet 4
10G_SFP_SDA1: P2.A38(10G_SFP_SDA1) ; also on sheet 4
10G_SFP_SDA2: P2.A33(10G_SFP_SDA2) ; also on sheet 4
10G_SFP_SDA3: P2.A32(10G_SFP_SDA3) ; also on sheet 4
25MHz_SYNC: U33.F11(CAL_CLK_OUT/JTAG_TDO) U34.F1(CAL_CLK_IN/JTAG_TDI)
25MHz_SYNC_XO: OSC1.3(OUT) U33.F1(CAL_CLK_IN/JTAG_TDI)
BATLOW#: P1.A27(BATLOW#) TP97.1
BIOS_DIS0#: P1.A34(BIOS_DIS0#/ESPI_SAFS) ; also on sheet 3
BIOS_DIS1#: P1.B88(BIOS_DIS1#/ESPI_BBS)
CB_RESET#: J23.9(Reset#) J28.A11(~{PERST}) P1.B50(CB_RESET#) R64.1 R468.1 ; also on sheet 3
CLK_122p88n: R545.2 ; also on sheet 5
CLK_122p88p: R4.2 ; also on sheet 5
CLK_161_BYP_N: R535.2 ; also on sheet 5
CLK_161_BYP_P: R534.2 ; also on sheet 5
CLK_SLOT2_N: J28.A14(REFCLK-) ; also on sheet 4
CLK_SLOT2_P: J28.A13(REFCLK+) ; also on sheet 4
COM_PWRBTN#: C976.1 P1.B12(PWRBTN#) ; also on sheet 4
CT_PWP3: C224.2 C225.2 C226.2 C1013.2 J5003.P2
FAN_PWM: J10.1(PWM) P1.B101(FAN_PWMOUT)
FAN_TACHIN: J10.2(SENSE) P1.B102(FAN_TACHIN) R509.1
GBE0_ACT#: P1.B2(GBE0_ACT#) R334.1
GBE0_CTREF: P1.A14(GBE0_CTREF)
GBE0_DN0: J5003.P10 P1.A12(GBE0_MDI0-)
GBE0_DN1: J5003.P8 P1.A9(GBE0_MDI1-)
GBE0_DN2: J5003.P6 P1.A6(GBE0_MDI2-)
GBE0_DN3: J5003.P4 P1.A2(GBE0_MDI3-)
GBE0_DP0: J5003.P9 P1.A13(GBE0_MDI0+)
GBE0_DP1: J5003.P7 P1.A10(GBE0_MDI1+)
GBE0_DP2: J5003.P5 P1.A7(GBE0_MDI2+)
GBE0_DP3: J5003.P3 P1.A3(GBE0_MDI3+)
GBE0_LINK100#: J5003.11 P1.A4(GBE0_LINK100#)
GBE0_LINK1000#: P1.A5(GBE0_LINK1000#) R333.1
GBE0_LINK#: P1.A8(GBE0_LINK#)
GPO2: J23.27(ModPrs#) P1.B57(GPO2) R506.1
HUB_CFGSEL0: R66.1 U10004.24(SCL/SMBCLK/CFG_SEL0)
HUB_CFGSEL1: R65.1 U10004.25(HS_IND/CFG_SEL1)
HUB_CRFILT: C114.1 U10004.14(CRFILT)
HUB_NONREM0: R61.2 U10004.28(SUSP_IND/LOCAL_PWR/NON_REM0)
HUB_NONREM1: R479.1 U10004.22(SDA/SMBDATA/NON_REM1)
HUB_PLLFILT: C108.1 U10004.34(PLLFILT)
HUB_RBIAS: R67.1 U10004.35(RBIAS)
HUB_RESET#: C104.1 R63.2 R64.2 U10004.26(~{RESET})
HUB_VBUSDET: R60.2 U10004.27(VBUS_DET)
HUB_XTAL1: C112.1 R68.1 U10004.33(XTAL1/CLKIN) Y1.1
HUB_XTAL2: C113.1 R68.2 U10004.32(XTAL2/CLKIN_EN) Y1.3
I2C_SCL: J23.11(SCL) J28.B5(SMCLK) P1.B33(I2C_CK) ; also on sheet 4
I2C_SDA: J23.12(SDA) J28.B6(SMDAT) P1.B34(I2C_DAT) ; also on sheet 4
I1588_ALARM_OUT1_COM: J29.5(A3) P2.B83(RSVD)
I1588_ALARM_OUT2_COM: J29.7(A4) P2.B64(RSVD)
I1588_CLK_OUT_COM: J29.8(B4) P2.B77(RSVD)
I1588_TRIG_IN1_COM: J29.2(B1) P1.A49(RSVD)
IEEE_RCLK0_COM: J29.9(A5) P2.B97(RSVD)
LID#: P1.A103(LID#) TP115.1
MCU_USART1_RX: P1.A98(SER0_TX) ; also on sheet 3
NCSI_ARB_IN: P1.B98(NCSI_ARB_IN) TP113.1
NCSI_ARB_OUT: P1.B99(NCSI_ARB_OUT) TP114.1
NCSI_CLK_IN: P1.B91(NCSI_CLK_IN) TP107.1
NCSI_CRS_DV: P1.B94(NCSI_CRS_DV) TP110.1
NCSI_RXD0: P1.B93(NCSI_RXD0) TP109.1
NCSI_RXD1: P1.B92(NCSI_RXD1) TP108.1
NCSI_TRI_EN: P1.B89(NCSI_TRI_EN) TP106.1
NCSI_TX_EN: P1.A84(NCSI_TX_EN) TP105.1
NCSI_TXD0: P1.B96(NCSI_TXD0) TP112.1
NCSI_TXD1: P1.B95(NCSI_TXD1) TP111.1
OC#1: U10004.13(~{OCS1})
OC#2: U10004.17(~{OCS2})
OC#3: U10004.19(~{OCS3})
OC#4: U10004.21(~{OCS4})
PCIE_CKREF_N: P1.A89(PCIE_CK_REF-) ; also on sheet 4
PCIE_CKREF_P: P1.A88(PCIE_CK_REF+) ; also on sheet 4
PCIE_RXN0: P1.B69(PCIE_RX0-) ; also on sheet 3
PCIE_RXN1: P1.B65(PCIE_RX1-) ; also on sheet 3
PCIE_RXN2: P1.B62(PCIE_RX2-) ; also on sheet 3
PCIE_RXN3: P1.B59(PCIE_RX3-) ; also on sheet 3
PCIE_RXN4: C330.1 P1.B56(PCIE_RX4-)
PCIE_RXN5: C985.1 P1.B53(PCIE_RX5-)
PCIE_RXN6: P2.A20(PCIE_RX6-)
PCIE_RXN7: P2.A23(PCIE_RX7-)
PCIE_RXN8: J28.A17(PERN0) P1.B72(PCIE_RX8-)
PCIE_RXN9: J28.A22(PERN1) P1.B75(PCIE_RX9-)
PCIE_RXN10: J28.A26(PERN2) P1.B78(PCIE_RX10-)
PCIE_RXN11: J28.A30(PERN3) P1.B82(PCIE_RX11-)
PCIE_RXN12: J28.A36(PERN4) P1.B40(PCIE_RX12-)
PCIE_RXN13: J28.A40(PERN5) P1.B37(PCIE_RX13-)
PCIE_RXN14: J28.A44(PERN6) P1.B26(PCIE_RX14-)
PCIE_RXN15: J28.A48(PERN7) P1.B23(PCIE_RX15-)
PCIE_RXN16: P2.A53(PCIE_RX16-) ; also on sheet 4
PCIE_RXN17: P2.A56(PCIE_RX17-) ; also on sheet 4
PCIE_RXN18: P2.A59(PCIE_RX18-) ; also on sheet 4
PCIE_RXN19: P2.A62(PCIE_RX19-) ; also on sheet 4
PCIE_RXN20: P2.A66(PCIE_RX20-)
PCIE_RXN21: P2.A69(PCIE_RX21-)
PCIE_RXN22: P2.A72(PCIE_RX22-)
PCIE_RXN23: P2.A75(PCIE_RX23-)
PCIE_RXN24: P2.A79(PCIE_RX24-)
PCIE_RXN25: P2.A82(PCIE_RX25-)
PCIE_RXN26: P2.A86(PCIE_RX26-)
PCIE_RXN27: P2.A89(PCIE_RX27-)
PCIE_RXN28: P2.A92(PCIE_RX28-)
PCIE_RXN29: P2.A95(PCIE_RX29-)
PCIE_RXN30: P2.A99(PCIE_RX30-)
PCIE_RXN31: P2.A102(PCIE_RX31-)
PCIE_RXP0: P1.B68(PCIE_RX0+) ; also on sheet 3
PCIE_RXP1: P1.B64(PCIE_RX1+) ; also on sheet 3
PCIE_RXP2: P1.B61(PCIE_RX2+) ; also on sheet 3
PCIE_RXP3: P1.B58(PCIE_RX3+) ; also on sheet 3
PCIE_RXP4: C331.1 P1.B55(PCIE_RX4+)
PCIE_RXP5: C986.1 P1.B52(PCIE_RX5+)
PCIE_RXP6: P2.A19(PCIE_RX6+)
PCIE_RXP7: P2.A22(PCIE_RX7+)
PCIE_RXP8: J28.A16(PERP0) P1.B71(PCIE_RX8+)
PCIE_RXP9: J28.A21(PERP1) P1.B74(PCIE_RX9+)
PCIE_RXP10: J28.A25(PERP2) P1.B77(PCIE_RX10+)
PCIE_RXP11: J28.A29(PERP3) P1.B81(PCIE_RX11+)
PCIE_RXP12: J28.A35(PERP4) P1.B39(PCIE_RX12+)
PCIE_RXP13: J28.A39(PERP5) P1.B36(PCIE_RX13+)
PCIE_RXP14: J28.A43(PERP6) P1.B25(PCIE_RX14+)
PCIE_RXP15: J28.A47(PERP7) P1.B22(PCIE_RX15+)
PCIE_RXP16: P2.A52(PCIE_RX16+) ; also on sheet 4
PCIE_RXP17: P2.A55(PCIE_RX17+) ; also on sheet 4
PCIE_RXP18: P2.A58(PCIE_RX18+) ; also on sheet 4
PCIE_RXP19: P2.A61(PCIE_RX19+) ; also on sheet 4
PCIE_RXP20: P2.A65(PCIE_RX20+)
PCIE_RXP21: P2.A68(PCIE_RX21+)
PCIE_RXP22: P2.A71(PCIE_RX22+)
PCIE_RXP23: P2.A74(PCIE_RX23+)
PCIE_RXP24: P2.A78(PCIE_RX24+)
PCIE_RXP25: P2.A81(PCIE_RX25+)
PCIE_RXP26: P2.A85(PCIE_RX26+)
PCIE_RXP27: P2.A88(PCIE_RX27+)
PCIE_RXP28: P2.A91(PCIE_RX28+)
PCIE_RXP29: P2.A94(PCIE_RX29+)
PCIE_RXP30: P2.A98(PCIE_RX30+)
PCIE_RXP31: P2.A101(PCIE_RX31+)
PCIE_TXN0: P1.A69(PCIE_TX0-) ; also on sheet 3
PCIE_TXN1: P1.A65(PCIE_TX1-) ; also on sheet 3
PCIE_TXN2: P1.A62(PCIE_TX2-) ; also on sheet 3
PCIE_TXN3: P1.A59(PCIE_TX3-) ; also on sheet 3
PCIE_TXN4: P1.A56(PCIE_TX4-) U32.3(TXn)
PCIE_TXN5: P1.A53(PCIE_TX5-) U2028.3(TXn)
PCIE_TXN6: P2.B20(PCIE_TX6-)
PCIE_TXN7: P2.B23(PCIE_TX7-)
PCIE_TXN8: J28.B15(PETN0) P1.A72(PCIE_TX8-)
PCIE_TXN9: J28.B20(PETN1) P1.A75(PCIE_TX9-)
PCIE_TXN10: J28.B24(PETN2) P1.A78(PCIE_TX10-)
PCIE_TXN11: J28.B28(PETN3) P1.A82(PCIE_TX11-)
PCIE_TXN12: J28.B34(PETN4) P1.A40(PCIE_TX12-)
PCIE_TXN13: J28.B38(PETN5) P1.A37(PCIE_TX13-)
PCIE_TXN14: J28.B42(PETN6) P1.A26(PCIE_TX14-)
PCIE_TXN15: J28.B46(PETN7) P1.A23(PCIE_TX15-)
PCIE_TXN16: P2.B53(PCIE_TX16-) ; also on sheet 4
PCIE_TXN17: P2.B56(PCIE_TX17-) ; also on sheet 4
PCIE_TXN18: P2.B59(PCIE_TX18-) ; also on sheet 4
PCIE_TXN19: P2.B62(PCIE_TX19-) ; also on sheet 4
PCIE_TXN20: P2.B66(PCIE_TX20-)
PCIE_TXN21: P2.B69(PCIE_TX21-)
PCIE_TXN22: P2.B72(PCIE_TX22-)
PCIE_TXN23: P2.B75(PCIE_TX23-)
PCIE_TXN24: P2.B79(PCIE_TX24-)
PCIE_TXN25: P2.B82(PCIE_TX25-)
PCIE_TXN26: P2.B86(PCIE_TX26-)
PCIE_TXN27: P2.B89(PCIE_TX27-)
PCIE_TXN28: P2.B92(PCIE_TX28-)
PCIE_TXN29: P2.B95(PCIE_TX29-)
PCIE_TXN30: P2.B99(PCIE_TX30-)
PCIE_TXN31: P2.B102(PCIE_TX31-)
PCIE_TXP0: P1.A68(PCIE_TX0+) ; also on sheet 3
PCIE_TXP1: P1.A64(PCIE_TX1+) ; also on sheet 3
PCIE_TXP2: P1.A61(PCIE_TX2+) ; also on sheet 3
PCIE_TXP3: P1.A58(PCIE_TX3+) ; also on sheet 3
PCIE_TXP4: P1.A55(PCIE_TX4+) U32.2(TXp)
PCIE_TXP5: P1.A52(PCIE_TX5+) U2028.2(TXp)
PCIE_TXP6: P2.B19(PCIE_TX6+)
PCIE_TXP7: P2.B22(PCIE_TX7+)
PCIE_TXP8: J28.B14(PETP0) P1.A71(PCIE_TX8+)
PCIE_TXP9: J28.B19(PETP1) P1.A74(PCIE_TX9+)
PCIE_TXP10: J28.B23(PETP2) P1.A77(PCIE_TX10+)
PCIE_TXP11: J28.B27(PETP3) P1.A81(PCIE_TX11+)
PCIE_TXP12: J28.B33(PETP4) P1.A39(PCIE_TX12+)
PCIE_TXP13: J28.B37(PETP5) P1.A36(PCIE_TX13+)
PCIE_TXP14: J28.B41(PETP6) P1.A25(PCIE_TX14+)
PCIE_TXP15: J28.B45(PETP7) P1.A22(PCIE_TX15+)
PCIE_TXP16: P2.B52(PCIE_TX16+) ; also on sheet 4
PCIE_TXP17: P2.B55(PCIE_TX17+) ; also on sheet 4
PCIE_TXP18: P2.B58(PCIE_TX18+) ; also on sheet 4
PCIE_TXP19: P2.B61(PCIE_TX19+) ; also on sheet 4
PCIE_TXP20: P2.B65(PCIE_TX20+)
PCIE_TXP21: P2.B68(PCIE_TX21+)
PCIE_TXP22: P2.B71(PCIE_TX22+)
PCIE_TXP23: P2.B74(PCIE_TX23+)
PCIE_TXP24: P2.B78(PCIE_TX24+)
PCIE_TXP25: P2.B81(PCIE_TX25+)
PCIE_TXP26: P2.B85(PCIE_TX26+)
PCIE_TXP27: P2.B88(PCIE_TX27+)
PCIE_TXP28: P2.B91(PCIE_TX28+)
PCIE_TXP29: P2.B94(PCIE_TX29+)
PCIE_TXP30: P2.B98(PCIE_TX30+)
PCIE_TXP31: P2.B101(PCIE_TX31+)
PCIE_WAKE#: P1.B66(WAKE0#)
PHY1_RECOVERED_CLK: P2.B63(RSVD) ; also on sheet 5
PPS: R541.2 ; also on sheet 5
PPS_IN_UFL: R560.2 ; also on sheet 5
PRSNT_SLOT2_B: J28.B17(~{PRSNT2}_1) J28.B31(~{PRSNT2}_2) J28.B48(~{PRSNT2}_3) R561.2
PWM: J5013.1(PWM) J5016.1(PWM)
PWON1: U10004.12(PRTPWR1)
PWON2: U10004.16(PRTPWR2)
PWON3: U10004.18(PRTPWR3)
PWON4: U10004.20(PRTPWR4)
PWR_OK: P1.B24(PWR_OK) ; also on sheet 4
SATA0_RXN: P1.A20(SATA0_RX-) U29.5(RXn)
SATA0_RXP: P1.A19(SATA0_RX+) U29.6(RXp)
SATA0_TXN: P1.A17(SATA0_TX-) U29.3(TXn)
SATA0_TXP: P1.A16(SATA0_TX+) U29.2(TXp)
SATA1_RXN: P1.B20(SATA1_RX-) U31.5(RXn)
SATA1_RXP: P1.B19(SATA1_RX+) U31.6(RXp)
SATA1_TXN: P1.B17(SATA1_TX-) U31.3(TXn)
SATA1_TXP: P1.B16(SATA1_TX+) U31.2(TXp)
SATA_ACT#: P1.A28(SATA_ACT#)
SD_CD: P1.B63(GPO3/SD_CD) U6.9(Cd)
SD_CLK: P1.A93(GPO0) U6.5(CLK)
SD_CMD: P1.B54(GPO1) U6.3(CMD)
SD_D0: P1.A54(GPI0) U6.7(D0)
SD_D1: P1.A63(GPI1) U6.8(D1)
SD_D2: P1.A67(GPI2) U6.1(D2)
SD_D3: P1.A85(GPI3) U6.2(CD/D3)
SENSE: J5013.2(SENSE) J5016.2(SENSE)
SER0_RX: P1.A99(SER0_RX) ; also on sheet 3
SER1_RX: P1.A102(CAN0/SER1_RX) ; also on sheet 3
SER1_TX: P1.A101(CAN0/SER1_TX) ; also on sheet 3
SLEEP#: P1.B103(SLEEP#) TP116.1
SLOT2_WAKE_B: J28.B11(~{WAKE}) TP117.1(TP)
SLP_S3#: P1.A15(SUS_S3#)
SLP_S4#: P1.A18(SUS_S4#)
SMB_ALERT#: P1.B15(SMB_ALERT#) U33.H1(INT_N) U34.H1(INT_N)
SMB_CLK: P1.B13(SMB_CK) U33.H11(SDC) U34.H11(SDC) ; also on sheet 3 5
SMB_SDA: P1.B14(SMB_DAT) U33.G11(SDA) U34.G11(SDA) ; also on sheet 3 5
SPI_CLK: P1.A94(SPI_CLK) ; also on sheet 3
SPI_CS#: P1.B97(SPI_CS#) ; also on sheet 3
SPI_MISO: P1.A92(SPI_MISO) ; also on sheet 3
SPI_MOSI: P1.A95(SPI_MOSI) ; also on sheet 3
SPI_POWER: P1.A91(SPI_POWER) ; also on sheet 3
SPKR: P1.B32(SPKR) TP101.1
SUS_S5#: P1.A24(SUS_S5#) TP99.1 ; also on sheet 4
SYS_RESET#: P1.B49(SYS_RESET#) ; also on sheet 3 5
THRM: P1.B35(THRM#) TP103.1
THRMTRIP#: P1.A35(THRMTRIP#) TP102.1
TYPE0#: P2.A54(TYPE0#)
TYPE1#: P2.A57(TYPE1#)
TYPE2#: P2.B57(TYPE2#)
USB0_DN: P1.A45(USB0-) ; also on sheet 3
USB0_DP: P1.A46(USB0+) ; also on sheet 3
USB1_DN: P1.B45(USB1-) ; also on sheet 3
USB1_DP: P1.B46(USB1+) ; also on sheet 3
USB2_DN: P1.A42(USB2-) ; also on sheet 3
USB2_DP: P1.A43(USB2+) ; also on sheet 3
USB3_DN: P1.B42(USB3-) U10004.30(USBUP_DM)
USB3_DP: P1.B43(USB3+) U10004.31(USBUP_DP)
USB_N1: U10004.1(USBDN1_DM)
USB_N2: U10004.3(USBDN2_DM) ; also on sheet 3
USB_N3: U10004.6(USBDN3_DM) ; also on sheet 3
USB_N4: U10004.8(USBDN4_DM) ; also on sheet 3
USB_P1: U10004.2(USBDN1_DP)
USB_P2: U10004.4(USBDN2_DP) ; also on sheet 3
USB_P3: U10004.7(USBDN3_DP) ; also on sheet 3
USB_P4: U10004.9(USBDN4_DP) ; also on sheet 3
USB_SSRX_N0: P2.A3(USB_SSRX0-) ; also on sheet 3
USB_SSRX_N1: P2.A6(USB_SSRX1-) ; also on sheet 3
USB_SSRX_N2: P2.A9(USB_SSRX2-) ; also on sheet 3
USB_SSRX_N3: P2.A12(USB_SSRX3-)
USB_SSRX_P0: P2.A4(USB_SSRX0+) ; also on sheet 3
USB_SSRX_P1: P2.A7(USB_SSRX1+) ; also on sheet 3
USB_SSRX_P2: P2.A10(USB_SSRX2+) ; also on sheet 3
USB_SSRX_P3: P2.A13(USB_SSRX3+)
USB_SSTX_N0: P2.B3(USB_SSTX0-) ; also on sheet 3
USB_SSTX_N1: P2.B6(USB_SSTX1-) ; also on sheet 3
USB_SSTX_N2: P2.B9(USB_SSTX2-) ; also on sheet 3
USB_SSTX_N3: P2.B12(USB_SSTX3-)
USB_SSTX_P0: P2.B4(USB_SSTX0+) ; also on sheet 3
USB_SSTX_P1: P2.B7(USB_SSTX1+) ; also on sheet 3
USB_SSTX_P2: P2.B10(USB_SSTX2+) ; also on sheet 3
USB_SSTX_P3: P2.B13(USB_SSTX3+)
V_2.5_RT1: C1065.1 C1066.1 C1067.1 C1068.1 C1069.1 C1070.1 C1093.1 C1114.1 FB37.2 OSC1.1(EN) OSC1.4(VCC) R550.2 R552.2 R558.2 U33.C3(VDD) U33.C9(VDD) U33.D3(VDD) U33.D4(VDD) U33.D5(VDD) U33.D7(VDD) U33.D8(VDD) U33.D9(VDD) U33.H3(VDD) U33.H4(VDD) U33.H5(VDD) U33.H7(VDD) U33.H8(VDD) U33.H9(VDD) U33.J3(VDD) U33.J9(VDD)
V_2.5_RT1_UNFLT: C1090.1 FB37.1 U10017.3(OUT)
V_2.5_RT2: C1071.1 C1072.1 C1073.1 C1074.1 C1075.1 C1076.1 C1115.1 FB38.2 R554.2 R556.2 R559.2 U34.C3(VDD) U34.C9(VDD) U34.D3(VDD) U34.D4(VDD) U34.D5(VDD) U34.D7(VDD) U34.D8(VDD) U34.D9(VDD) U34.H3(VDD) U34.H4(VDD) U34.H5(VDD) U34.H7(VDD) U34.H8(VDD) U34.H9(VDD) U34.J3(VDD) U34.J9(VDD)
V_2.5_RT2_UNFLT: C1089.1 FB38.1 U3.3(OUT)
V_5_SB: P1.B84(VCC_5V_SBY) P1.B85(VCC_5V_SBY) P1.B86(VCC_5V_SBY) P1.B87(VCC_5V_SBY) ; also on sheet 4
WAKE1#: P1.B67(WAKE1#) TP104.1
WDT: P1.B27(WDT) TP100.1
N18649190: C330.2 U32.5(RXn)
N18649196: C331.2 U32.6(RXp)
N18679523: C985.2 U2028.5(RXn)
N18679529: C986.2 U2028.6(RXp)
N18738489: J5003.12 R333.2
N18738529: J5003.14 R334.2
N18807494: J23.28(Int#) TP122.1(TP)
N18807499: J23.31(LPMode) TP123.1(TP)
N18893006: C1064.1 R510.2
N18975097: P2.A77(RSVD) TP126.1
N18975108: P2.A97(RSVD) TP127.1
N18989083: J29.3(A2) R540.2
N18990072: J28.A5(JTAG_TCK) R4.1
N18990245: J29.1(A1) R542.2
N18990572: J28.A8(JTAG_TMS) R544.1 R560.1
N18990620: J28.A6(JTAG_TDI) R545.1
N19005504: R550.1 R551.1 U33.D11(ADDR0)
N19005518: R552.1 R553.1 U33.D1(ADDR1/JTAG_TRS)
N19007966: R554.1 R555.1 U34.D11(ADDR0)
N19007970: R556.1 R557.1 U34.D1(ADDR1/JTAG_TRS)
N19008748: R558.1 U33.G1(EN_SMB)
N19008911: R559.1 U34.G1(EN_SMB)
N19009298: TP132.1(TP) U33.E1(ALL_DONE_N)
N19009309: TP133.1(TP) U33.E11(READ_EN_N)
N19009342: TP134.1(TP) U34.E1(ALL_DONE_N)
N19009344: TP135.1(TP) U34.E11(READ_EN_N)
N19031604: J28.B81(~{PRSNT2}_4) R561.1

Not connected (* = marked no-connect by the designer): J28 A7(JTAG_TDO)* A19(RSVD3)* A32(RSVD4)* A33(RSVD5)* A50(RESERVED) A52(PERP8) A53(PERN8) A56(PERP9) A57(PERN9) A60(PERP10) A61(PERN10) A64(PERP11) A65(PERN11) A68(PERP12) A69(PERN12) A72(PERP13) A73(PERN13) A76(PERP16) A77(PERN16) A80(PERP15) A81(PERN15) B9(JTAG_~{TRST})* B12(RSVD1)* B30(RSVD2)* B50(PETP8) B51(PETN8) B54(PETP9) B55(PETN9) B58(PETP10) B59(PETN10) B62(PETP11) B63(PETN11) B66(PETP12) B67(PETN12) B70(PETP13) B71(PETN13) B74(PETP14) B75(PETN14) B78(PETP15) B79(PETP15) B82(RESERVED); J41 1; J42 1; J43 1; J44 1; J45 1; J5003 P1; P1 A29(RSVD)* A30(RSVD)* A32(RSVD)* A33(RSVD)* A44(USB_2_3_OC#)* A48(RSVD)* A50(LPC_SERIRQ/ESPI_CS1#)* A86(RSVD)* A87(RSVD)* A96(TPM_PP) A97(TYPE10#)* B3(LPC_FRAME#/ESPI_CS0#)* B4(LPC_AD0/ESPI_IO_0)* B5(LPC_AD0/ESPI_IO_1)* B6(LPC_AD0/ESPI_IO_2)* B7(LPC_AD0/ESPI_IO_3)* B8(LPC_DRQ0#/ESPI_ALERT0#)* B9(LPC_DRQ1#/ESPI_ALERT1#)* B10(LPC_CLK/ESPI_CK)* B18(SUS_STAT#/ESPI_RESET#)* B28(RSVD)* B29(RSVD)* B30(RSVD)* B44(USB_0_1_OC#)* B47(ESPI_EN)* B48(RSVD)*; P2 A63(RSVD) A64(RSVD) A67(RAPID_SHUTDOWN_(RSVD)) A83(RSVD) B36(RSVD) B37(RSVD) B54(RSVD); U33 D2(TEST1/JTAG_TMS) D10(TEST0/JTAG_TCK) E2(TEST3) E10(TEST2) H2(TEST5) H10(TEST4); U34 D2(TEST1/JTAG_TMS) D10(TEST0/JTAG_TCK) E2(TEST3) E10(TEST2) F11(CAL_CLK_OUT/JTAG_TDO) H2(TEST5) H10(TEST4)

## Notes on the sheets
sheet 1
- SMB I2C devices -
  0x22 - COM 4x25Gbps TX retimer
  0x23 - COM 4x25Gbps RX retime
  STM32 MCU (multi master)
  0x5B - IDT CLK GEN
  0x50 - IDT CLK EEPROM (not assembled)
  0x4C - OCXO DAC (not assembled)
  0x4A - LX2-COM Temperature sensor
  0x4C - LX2-COM Unassembled temp sensor
  0x7F - LX2-COM I2C switch
- COM express type 7 AB connector
- COM express type 7 AB connector
- The below RC circuit is single ended filter for the
  MDC clock coming from the COM module.
  Since COM express PCB rev 1.4 this is not required anymore since the termination is on the COM express.
- SD1 clock bypass for 1588 sync
- SD Card 1.8v/3.3v support -
  GPI0 - SD D0
  GPI1 - SD D1
  GPI2 - SD D2
  GPI3 - SD D3
  GPO0 - SD CLK
  GPO1 - SD CMD
  GPO3 - SD CD#
- IEEE-1588 Access Header
- Bottom left
- Bottom middle
- Bottom right
- Upper left
- Bottom right
sheet 2
- 4 ports USB 2.0 hub
- 3 x SATA gen 3.0 connectors
- Note on U32 and U2028 connectors -
  TX AC-caps are on module since those are SERDES lines that are defined
  as PCIe in COM-express and repurposed as SATA via SD2 protocol config #5.
  Due to that RX AC-caps must be on carrier board
- micro SD connector (bootable)
- OCS ARE INTERNAL PULL-UP, 5.5V TOLERANT
- POWER ON OUTPUTS ARE ACTIVE HIGH
- Note on U29 and U31 connectors
  Per the COM express type 7 spec; the native COM express type 7 SATA ports TX/RX AC-caps are on module.
- NON-REM[1:0]
  '00' - ALL REMOVABLE
  '01' - PORT 1 IS NON-REMOVABLE
  '10' - PORTS 1 AND 2 ARE NON-REMOVABLE
  '11' - PORTS 1, 2 AND 3 ARE NON-REMOVABLE
  IN THIS DESIGN NON-REM[1:0] ARE SET TO
  '01' - PORT 1 IS NON-REMOVABLE
- 3 x Standard 4 pin FAN headers
  with one supporting PWM and TACH.
- Notes -
  1. The FAN connector can accomodate 2 and 3 pin header fans since the plastic part can accomodate that.
  2. LX2K-COM express type 7 rev 1.3 does not support PWM and TACH; only on rev 1.4 and onwords
- TACH pull-up is a workaround for LX2160 COM rev 1.3
- PCI express 8 lanes connector - open slot
- GBE0_CTREF can be left floating
- QSFP28 connector
- Split to 3 domains
- ADDR0, ADDR1 floating - I2C address is 0x22
- ADDR0, ADDR1 floating - I2C address is 0x22
- Bug notice -
  ModSel# signal in rev 1.1 is floating where it must be grounded in order
  for the QSFP module I2C to be selected.
  As a workaround ModSel# is fixed by externally wiring TP121 to GND.
  This bug is fixed in future revisions.
